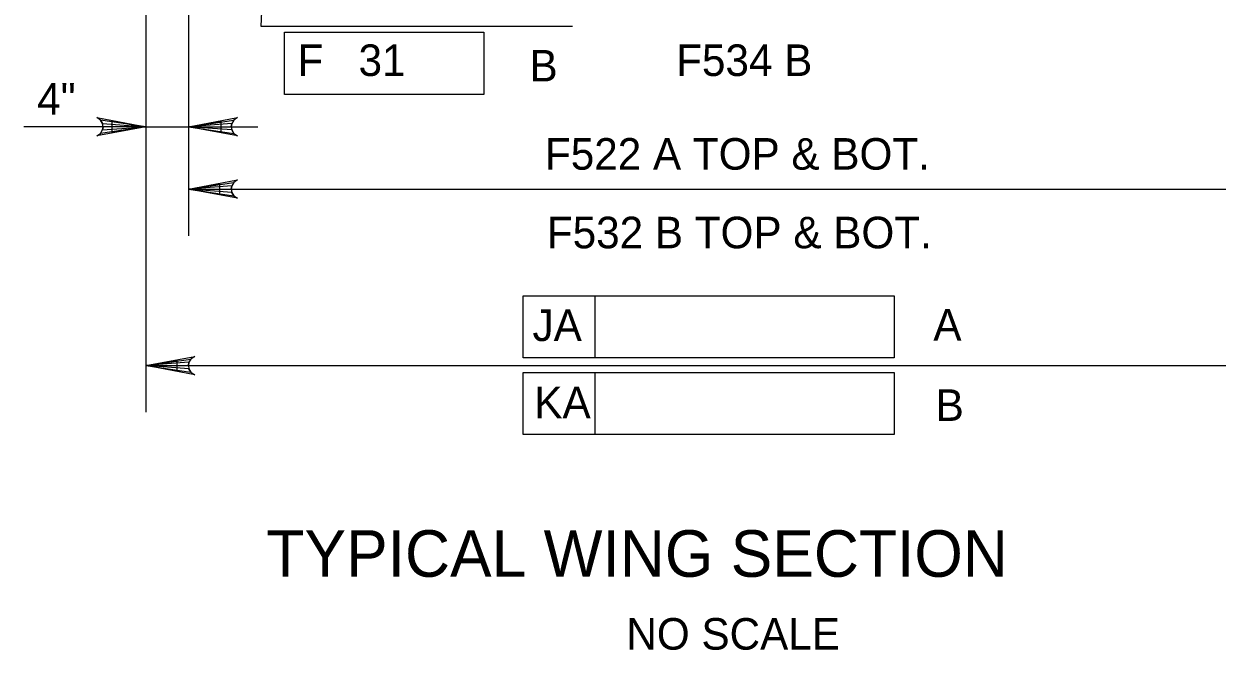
# Model space of a CAD drawing. Extents: x 638340 to 640242, y 295465 to 298435.
# Drawn here: x 639084.5 to 639197.8, y 296352.7 to 296412.2 of the extents above; entities that cross this region are included whole.
import ezdxf

# ---------------------------------------------------------------- set-up
doc = ezdxf.new("R2010")
doc.units = 0
for name, color, linetype in [('4', 7, 'Continuous'), ('Level 3', 7, 'Continuous'), ('Level 4', 7, 'Continuous')]:
    doc.layers.add(name, color=color, linetype=linetype)

msp = doc.modelspace()

# ---------------------------------------------------------------- linework, layer by layer
at = {"layer": 'Level 4'}
for p, q in [((639108.24, 296438.86), (639106.97, 296412)), ((639096.03, 296433.24), (639096.03, 296375.34)), ((639100.09, 296423.31), (639100.09, 296392.1)), ((639106.97, 296412), (639136.57, 296412)), ((639109.22, 296411.42), (639128.13, 296411.42)), ((639109.22, 296405.52), (639109.22, 296411.42)), ((639128.13, 296411.42), (639128.13, 296405.52)), ((639128.13, 296405.52), (639109.22, 296405.52)), ((639096.03, 296402.45), (639084.46, 296402.45)), ((639096.03, 296402.45), (639106.67, 296402.45)), ((639100.09, 296396.53), (639206.03, 296396.53)), ((639131.88, 296386.37), (639167.12, 296386.37)), ((639131.88, 296380.48), (639131.88, 296386.37)), ((639138.71, 296380.48), (639138.71, 296386.37)), ((639167.12, 296386.37), (639167.12, 296380.48)), ((639167.12, 296380.48), (639131.88, 296380.48)), ((639096.03, 296379.76), (639210.09, 296379.76)), ((639131.88, 296379.1), (639167.12, 296379.1)), ((639131.88, 296373.21), (639131.88, 296379.1)), ((639138.71, 296373.21), (639138.71, 296379.1)), ((639167.12, 296379.1), (639167.12, 296373.21)), ((639167.12, 296373.21), (639131.88, 296373.21))]:
    msp.add_line(p, q, dxfattribs=at)
for points in [[(639096.03, 296402.45), (639091.38, 296401.58), (639091.74, 296401.82), (639091.93, 296402.14), (639091.98, 296402.45), (639091.93, 296402.76), (639091.74, 296403.07), (639091.38, 296403.32), (639096.03, 296402.45), (639091.74, 296403.07), (639091.93, 296402.76), (639096.03, 296402.45), (639091.98, 296402.45), (639091.93, 296402.14), (639096.03, 296402.45), (639091.74, 296401.82)], [(639100.09, 296402.45), (639104.75, 296403.32), (639104.39, 296403.07), (639104.2, 296402.76), (639104.15, 296402.45), (639104.2, 296402.14), (639104.39, 296401.82), (639104.75, 296401.58), (639100.09, 296402.45), (639104.39, 296401.82), (639104.2, 296402.14), (639100.09, 296402.45), (639104.15, 296402.45), (639104.2, 296402.76), (639100.09, 296402.45), (639104.39, 296403.07)], [(639100.09, 296396.53), (639104.75, 296397.4), (639104.39, 296397.15), (639104.2, 296396.84), (639104.15, 296396.53), (639104.2, 296396.21), (639104.39, 296395.9), (639104.75, 296395.65), (639100.09, 296396.53), (639104.39, 296395.9), (639104.2, 296396.21), (639100.09, 296396.53), (639104.15, 296396.53), (639104.2, 296396.84), (639100.09, 296396.53), (639104.39, 296397.15)], [(639096.03, 296379.76), (639100.69, 296380.63), (639100.33, 296380.38), (639100.14, 296380.07), (639100.09, 296379.76), (639100.14, 296379.44), (639100.33, 296379.13), (639100.69, 296378.88), (639096.03, 296379.76), (639100.33, 296379.13), (639100.14, 296379.44), (639096.03, 296379.76), (639100.09, 296379.76), (639100.14, 296380.07), (639096.03, 296379.76), (639100.33, 296380.38)]]:
    msp.add_lwpolyline(points, dxfattribs=at)
for points in [[(639092.81, 296402.94), (639092.81, 296401.96), (639095.76, 296402.45)], [(639103.18, 296401.96), (639103.18, 296402.94), (639100.23, 296402.45)], [(639103.04, 296397.02), (639103.04, 296396.04), (639100.09, 296396.53)], [(639098.98, 296380.25), (639098.98, 296379.27), (639096.03, 296379.76)]]:
    msp.add_lwpolyline(points, close=True, dxfattribs=at)

# ---------------------------------------------------------------- texts
at = {"layer": '4'}
for s, height, p in [('TYPICAL WING SECTION', 4.4294, (639107.49, 296359.69)), ('NO SCALE', 3, (639141.68, 296352.77))]:
    msp.add_text(s, height=height, dxfattribs=at).set_placement(p)
at = {"layer": 'Level 3'}
msp.add_text('4"', height=3, dxfattribs=at).set_placement((639085.72, 296403.59))
at = {"layer": 'Level 4'}
for s, height, p in [('F   31', 3, (639110.45, 296407.27)), ('B', 3, (639132.48, 296406.75)), ('F534 B', 3, (639146.41, 296407.27)), ('F522 A TOP & BOT.', 3.0001, (639133.95, 296398.37)), ('F532 B TOP & BOT.', 3.0001, (639134.13, 296390.9)), ('JA', 3, (639132.77, 296382.09)), ('A', 3, (639170.84, 296382.13)), ('KA', 3, (639132.94, 296374.76)), ('B', 3, (639171.06, 296374.5))]:
    msp.add_text(s, height=height, dxfattribs=at).set_placement(p)

doc.saveas('drawing.dxf')
